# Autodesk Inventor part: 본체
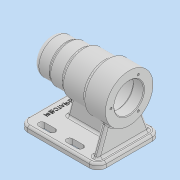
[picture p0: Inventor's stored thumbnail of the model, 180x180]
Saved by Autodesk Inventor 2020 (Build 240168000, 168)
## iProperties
Created: 2021-10
Part Number: 본체
Material: 일반
Document SubType Name: Modeling
Designer: user
Density: 1 g/cm^3
Appearance: 기본값
Author: user
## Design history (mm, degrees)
sketch "스케치1"
  geometry: L1 (0, 0)-(-112, 0); L2 (-112, 0)-(-112, 25); L3 (-112, 25)-(-88, 25); L4 (-88, 25)-(-88, 27); L5 (-88, 27)-(-66, 27); L6 (-66, 27)-(-66, 30); L7 (-66, 30)-(-32, 30); L8 (-32, 30)-(-32, 34); L9 (-32, 34)-(0, 34); L10 (0, 34)-(0, 21); L11 (0, 21)-(-15, 21); L12 (-15, 21)-(-15, 21); L13 (-18, 24)-(-66, 24); L14 (-69, 21)-(-69, 21); L15 (-69, 21)-(-80.7, 21); L16 (-81, 20.7)-(-81, 17.5); L17 (-81, 17.5)-(-98.7, 17.5); L18 (-99, 17.2)-(-99, 16); L19 (-99, 16)-(-102.7, 16); L20 (-103, 15.7)-(-103, 10.5); L21 (-103, 10.5)-(-103, 10.5); L22 (-106, 7.5)-(-106, 0); L23 (-112, 0)-(-106, 0); A1 r 3 centre (-103, 7.5) between (-103, 10.5) and (-106, 7.5); A2 r 0.3 centre (-102.7, 15.7) between (-102.7, 16) and (-103, 15.7); A3 r 0.3 centre (-98.7, 17.2) between (-98.7, 17.5) and (-99, 17.2); A4 r 0.3 centre (-80.7, 20.7) between (-80.7, 21) and (-81, 20.7); A5 r 3 centre (-66, 21) between (-66, 24) and (-69, 21); A6 r 3 centre (-18, 21) between (-15, 21) and (-18, 24); 3 further points
  constraints: 46 end point, 18 perpendicular, 12 point on circle, 12 tangent, 6 centre point, 3 equal radius, 3 vertical, 1 collinear, 1 horizontal
  dimensions: "d0" = 112 distance of L1.start L1.end; "d1" = 34 distance between parallel lines of L1 L9; "d2" = 30 distance between parallel lines of L1 L7; "d3" = 27 distance between parallel lines of L1 L5; "d4" = 25 distance between parallel lines of L1 L3; "d5" = 24 horizontal distance of L2.end L4.end; "d6" = 46 horizontal distance of L6.end L2.end; "d7" = 80 horizontal distance of L8.end L2.end; "d8" = 112 horizontal distance of L9.end L2.end; "d9" = 15 distance between parallel lines of L10 L12; "d10" = 21 distance between parallel lines of L1 L11; "d11" = 54 distance between parallel lines of L12 L14; "d12" = 24 distance between parallel lines of L1 L13; "d14" = 12 distance between parallel lines of L14 L16; "d15" = 21 distance between parallel lines of L1 L15; "d16" = 18 distance between parallel lines of L16 L18; "d17" = 17.5 distance between parallel lines of L1 L17; "d19" = 4 distance between parallel lines of L18 L20; "d20" = 3 distance between parallel lines of L20 L22; "d21" = 16 distance between parallel lines of L1 L19; "d22" = 10.5 distance between parallel lines of L1 L21; "d23" = 3 radius of A1; "d24" = 0.3 radius of A2; "d25" = 3 radius of A5
revolve "회전1" sketch "스케치1" stored, may be unused: angle "d26" = 90 deg
chamfer "모따기1" distance "d27" = 1; stored, may be unused: second distance "d28" = 2, angle "d29" = 45 deg
node "작업 평면1"
sketch "스케치2"
  geometry: L1 (0, -45)-(112, -45); L2 (112, -45)-(112, 45); L3 (112, 45)-(0, 45); L4 (0, 45)-(0, -45); 2 further points
  constraints: 8 end point, 2 parallel, 1 coincident, 1 horizontal, 1 midpoint, 1 perpendicular
  dimensions: "d31" = 112 distance between parallel lines of L4 L2; "d32" = 90 distance between parallel lines of L3 L1
extrude "돌출1" join sketch "스케치2" distance "d33" = 8; taper "d34" = 0 deg
sketch "스케치3"
  geometry: 2 further points
  constraints: 1 horizontal alignment
  dimensions: "d35" = 26 distance of point (0, 0) point (-26, 0)
hole "구멍1" sketch "스케치3" at (-26, 0) diameter "d36" = 3.242; stored, may be unused: countersink angle "d40" = 90 deg, drill point angle "d42" = 118 deg; dims "d37" = 8, "d38" = 4, "d39" = 2, "d41" = 11
sketch "스케치6"
  geometry: L1 (-85, -4)-(-8, -4); L2 (-8, -4)-(-8, 4); L3 (-8, 4)-(-85, 4); L4 (-85, 4)-(-85, -4); L5 (0, -45)-(0, 45) reference; 3 further points
  constraints: 8 end point, 2 midpoint, 2 parallel, 1 horizontal, 1 horizontal alignment, 1 perpendicular
  dimensions: "d50" = 8 distance between parallel lines of L1 L3; "d52" = 8 distance between parallel lines of L5 L2; "d97" = 77 distance from line of L1.end L4
extrude "돌출2" join sketch "스케치6" stored distance "d54" = 8; taper "d55" = 0 deg
node "작업 평면3"
sketch "스케치7"
  geometry: L1 (-23.409, -24.658)-(-37, -62); L2 (45, -62)-(-45, -62) reference; L3 (-45, -70)-(-45, -62) reference; A1 r 34 centre (0, 0) between (4, -33.764) and (-4, -33.764) reference; 1 further point
  constraints: 2 end point, 1 point on circle, 1 point on line
  dimensions: "d58" = 110 deg angle of L2 L1; "d60" = 8 distance from line of L3 L1.end
feature "리브1" sketch "스케치7" dims "d61" = 1, "d62" = 8, "d63" = 0, "d64" = 0, "d65" = 1, "d66" = 1
feature "면 기울기1" dims angle "d68" = 15 deg
fillet "모깎기1" dims "d69" = 8
fillet "모깎기2" dims "d70" = 3
sketch "스케치10"
  geometry: L1 (-92, -33)-(-77, -33); L2 (-92, -37.5)-(-77, -37.5); L3 (-77, -28.5)-(-92, -28.5); L4 (-52, -33)-(-37, -33); L5 (-52, -37.5)-(-37, -37.5); L6 (-37, -28.5)-(-52, -28.5); L7 (-92, 33)-(-77, 33); L8 (-92, 28.5)-(-77, 28.5); L9 (-77, 37.5)-(-92, 37.5); L10 (-52, 33)-(-37, 33); L11 (-52, 28.5)-(-37, 28.5); L12 (-37, 37.5)-(-52, 37.5); L13 (-112, 45)-(-112, -45) reference; L14 (-112, -45)-(0, -45) reference; A1 r 4.5 centre (-92, -33) between (-92, -28.5) and (-92, -37.5); A2 r 4.5 centre (-77, -33) between (-77, -37.5) and (-77, -28.5); A3 r 4.5 centre (-52, -33) between (-52, -28.5) and (-52, -37.5); A4 r 4.5 centre (-37, -33) between (-37, -37.5) and (-37, -28.5); A5 r 4.5 centre (-92, 33) between (-92, 37.5) and (-92, 28.5); A6 r 4.5 centre (-77, 33) between (-77, 28.5) and (-77, 37.5); A7 r 4.5 centre (-52, 33) between (-52, 37.5) and (-52, 28.5); A8 r 4.5 centre (-37, 33) between (-37, 28.5) and (-37, 37.5); 5 further points
  constraints: 32 end point, 16 point on circle, 16 tangent, 8 centre point, 5 parallel, 4 midpoint, 4 point on line, 1 horizontal
  dimensions: "d71" = 9 diameter of A2; "d72" = 15 distance of L4.start L4.end; "d73" = 9 diameter of A4; "d74" = 15 distance of L7.start L7.end; "d75" = 9 diameter of A6; "d76" = 15 distance of L10.start L10.end; "d77" = 9 diameter of A8; "d78" = 15 distance of L1.start L1.end; "d79" = 20 distance from line of L13 L1.start; "d80" = 25 distance of L4.start L1.end; "d81" = 20 distance from line of L13 L7.start; "d82" = 25 distance of L10.start L7.end; "d84" = 33 vertical distance of point (0, 0) point (-84.5, -33); "d85" = 33 vertical distance of L7.start point (0, 0)
extrude "돌출3" cut sketch "스케치10" distance "d86" = 8; taper "d87" = 0 deg
fillet "모깎기3" dims "d88" = 12
fillet "모깎기4" dims "d89" = 3
fillet "모깎기5" dims "d90" = 3
fillet "모깎기6" dims "d91" = 3
sketch "스케치11"
  geometry: L1 (-112, 33)-(-112, -33) reference; 2 further points
  constraints: 1 horizontal alignment, 1 other
  dimensions: "d94" = 12 distance from line of L1 point (-100, 0)
feature "엠보싱1" sketch "스케치11" dims "d0" = 112, "d1" = 34, "d2" = 30, "d3" = 27, "d4" = 25, "d5" = 24, "d6" = 46, "d7" = 80, "d8" = 112, "d9" = 15, "d10" = 21, "d11" = 54, "d12" = 24, "d14" = 12, "d15" = 21, "d16" = 18, "d17" = 17.5, "d19" = 4, "d20" = 3, "d21" = 16, "d22" = 10.5, "d23" = 3, "d24" = 0.3, "d25" = 3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
fillet "모깎기7" dims "d95" = 3
fillet "모깎기8" dims "d96" = 3
node "솔리드1"
pattern_circular "원형 패턴1" dims angle "d44" = 360 deg
mirror "미러1"
feature "A9D066F2-1C7D-4E18-AEED-F7BC21143FA4" dims "d36" = 3.242, "d37" = 8, "d38" = 4, "d39" = 2, "d40" = 90 deg, "d41" = 11, "d42" = 118 deg
other parameters: "d57" = -8
